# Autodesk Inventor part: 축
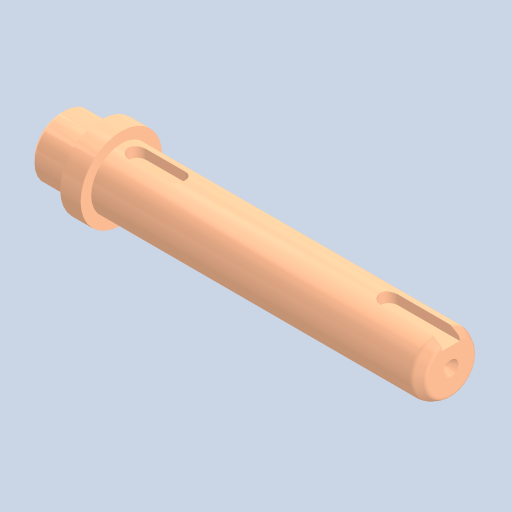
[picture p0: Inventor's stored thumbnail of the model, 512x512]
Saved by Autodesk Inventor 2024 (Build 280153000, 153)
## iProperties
Created: 2026-01
Part Number: 축
Material: 강철, 탄소
Document SubType Name: Modeling
Designer: 2-10
Density: 7.85 g/cm^3
Appearance: 기본값
Author: jhkim
Sending System: Autodesk Inventor 2026
Preprocessor: ST-DEVELOPER v20.1
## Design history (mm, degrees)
feature "솔리드1"
node "솔리드2"
